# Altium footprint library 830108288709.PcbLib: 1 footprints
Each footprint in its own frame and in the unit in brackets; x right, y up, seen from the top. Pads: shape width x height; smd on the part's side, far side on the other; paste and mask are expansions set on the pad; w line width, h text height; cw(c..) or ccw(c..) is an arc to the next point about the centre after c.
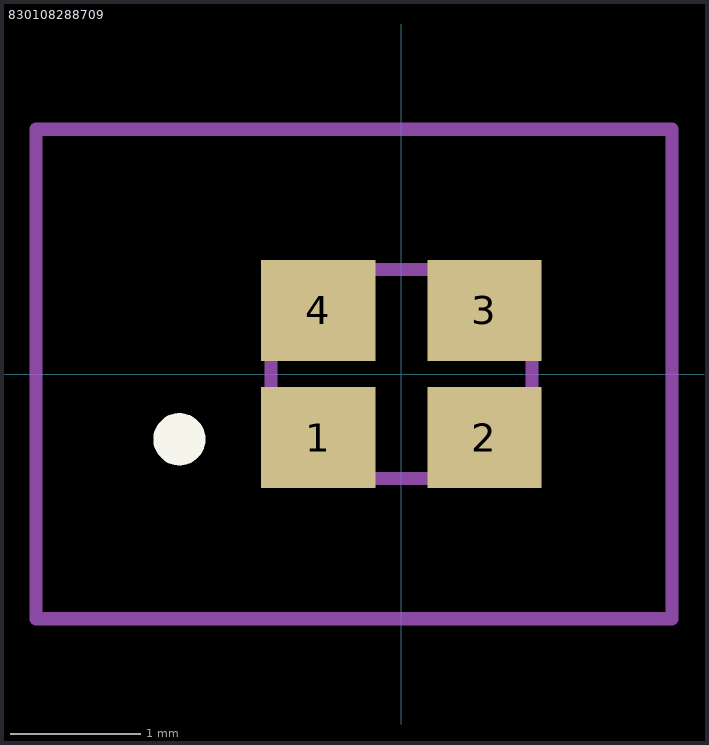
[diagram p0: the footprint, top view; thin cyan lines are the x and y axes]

## 830108288709 [mm]
pads (4):
  rect 0.875x0.775 smd: 1(-0.637,-0.487) 2(0.637,-0.487) 3(0.637,0.487) 4(-0.637,0.487)
Top Overlay:
  lines w0.2: -1.7,-0.6 cw(c-1.7,-0.5) -1.7,-0.4 ; -1.7,-0.6 -1.7,-0.6 ; -1.7,-0.6 ccw(c-1.7,-0.5) -1.7,-0.4 ; -1.7,-0.4 -1.7,-0.4
Mechanical 15:
  lines w0.1: -1,-0.8 1,-0.8 1,0.8 -1,0.8 -1,-0.8
Mechanical 20:
  lines w0.1: -2.8,-1.875 2.075,-1.875 2.075,1.875 -2.8,1.875 -2.8,-1.875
